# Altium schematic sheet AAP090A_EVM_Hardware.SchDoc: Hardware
size Letter; Date: Not shown in title block; ApprovedBy: Not shown in title block; CheckedBy: Not shown in title block; Author: Not shown in title block; CompanyName: Not shown in title block; DrawnBy: LDN; Engineer: Not shown in title block; Organization: Not shown in title block; Address1: Not shown in title block; Address2: Not shown in title block; Address3: Not shown in title block; Address4: Not shown in title block; DocumentNumber: 6; Revision: Use project parameter SCH_Rev; SheetNumber: 6; SheetTotal: 6; PageSetup: Record=PageOptions¦CenterHorizontal=True¦CenterVertical=True¦PrintScale=1.00¦XCorrection=1.00¦YCorrection=1.00¦PrintKind=0¦BorderSize=5000000¦LeftOffset=0¦BottomOffset=0¦Orientation=2¦PaperLength=1000¦PaperWidth=1000¦Scale=100¦PaperSource=15¦PrintQuality=600¦MediaType=1¦DitherType=10¦PaperKind=Letter¦PrintScaleMode=1
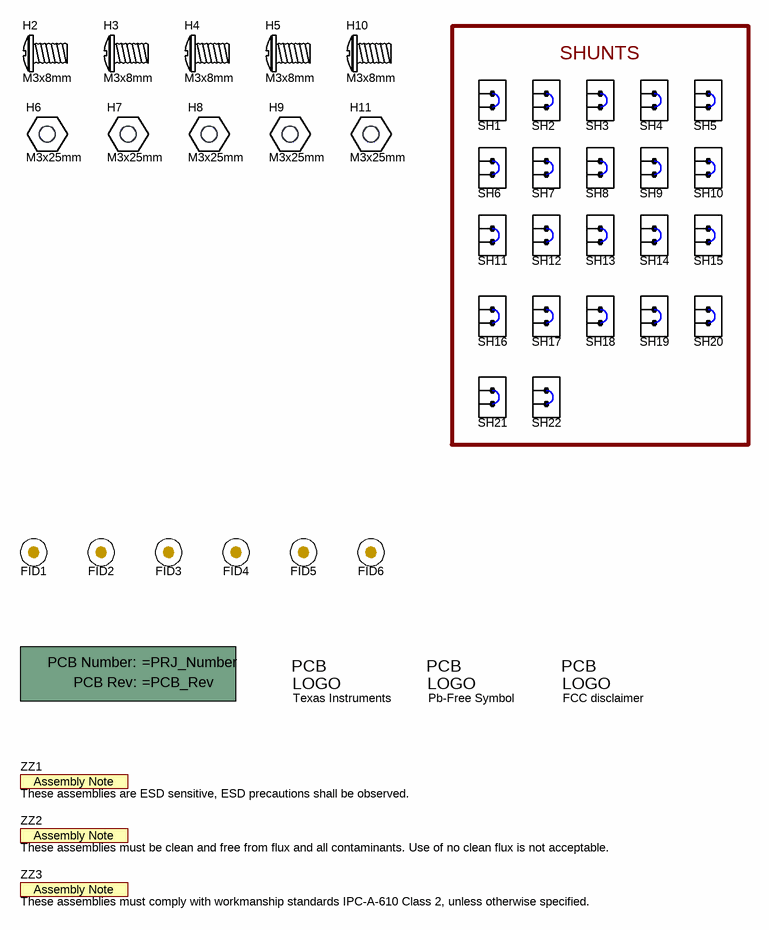
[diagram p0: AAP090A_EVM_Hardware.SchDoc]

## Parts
!PCB  Printed Circuit Board  (value not drawn)  (mechanical)
FID1  Fiducial  [Fiducial10-20]  (value not drawn)
FID2  Fiducial  [Fiducial10-20]  (value not drawn)
FID3  Fiducial  [Fiducial10-20]  (value not drawn)
FID4  Fiducial  [Fiducial10-20]  (value not drawn)
FID5  Fiducial  [Fiducial10-20]  (value not drawn)
FID6  Fiducial  [Fiducial10-20]  (value not drawn)
H2  M3x8mm  [APM_RM3X8MM 2701]
H3  M3x8mm  [APM_RM3X8MM 2701]
H4  M3x8mm  [APM_RM3X8MM 2701]
H5  M3x8mm  [APM_RM3X8MM 2701]
H6  M3x25mm  [Keystone24438]
H7  M3x25mm  [Keystone24438]
H8  M3x25mm  [Keystone24438]
H9  M3x25mm  [Keystone24438]
H10  M3x8mm  [APM_RM3X8MM 2701]
H11  M3x25mm  [Keystone24438]
Logo1  Texas Instruments  [TI_Stacked_Overlay_Small]  (no BOM)
Logo2  Pb-Free Symbol  [Pb-Free_Overlay_Medium]  (no BOM)
Logo3  FCC disclaimer  [FCC_disclaimer]  (no BOM)
SH1  SNT-100-BK-G  [SNT-100-BK-G]  (value not drawn)
SH2  SNT-100-BK-G  [SNT-100-BK-G]  (value not drawn)
SH3  SNT-100-BK-G  [SNT-100-BK-G]  (value not drawn)
SH4  SNT-100-BK-G  [SNT-100-BK-G]  (value not drawn)
SH5  SNT-100-BK-G  [SNT-100-BK-G]  (value not drawn)
SH6  SNT-100-BK-G  [SNT-100-BK-G]  (value not drawn)
SH7  SNT-100-BK-G  [SNT-100-BK-G]  (value not drawn)
SH8  SNT-100-BK-G  [SNT-100-BK-G]  (value not drawn)
SH9  SNT-100-BK-G  [SNT-100-BK-G]  (value not drawn)
SH10  SNT-100-BK-G  [SNT-100-BK-G]  (value not drawn)
SH11  SNT-100-BK-G  [SNT-100-BK-G]  (value not drawn)
SH12  SNT-100-BK-G  [SNT-100-BK-G]  (value not drawn)
SH13  SNT-100-BK-G  [SNT-100-BK-G]  (value not drawn)
SH14  SNT-100-BK-G  [SNT-100-BK-G]  (value not drawn)
SH15  SNT-100-BK-G  [SNT-100-BK-G]  (value not drawn)
SH16  SNT-100-BK-G  [SNT-100-BK-G]  (value not drawn)
SH17  SNT-100-BK-G  [SNT-100-BK-G]  (value not drawn)
SH18  SNT-100-BK-G  [SNT-100-BK-G]  (value not drawn)
SH19  SNT-100-BK-G  [SNT-100-BK-G]  (value not drawn)
SH20  SNT-100-BK-G  [SNT-100-BK-G]  (value not drawn)
SH21  SNT-100-BK-G  [SNT-100-BK-G]  (value not drawn)
SH22  SNT-100-BK-G  [SNT-100-BK-G]  (value not drawn)
ZZ1  These assemblies are ESD sensitive, ESD precautions shall be observed.  [AssemblyNote]  (no BOM)
ZZ2  These assemblies must be clean and free from flux and all contaminants. Use of no clean flux is not acceptable.  [AssemblyNote]  (no BOM)
ZZ3  These assemblies must comply with workmanship standards IPC-A-610 Class 2, unless otherwise specified.  [AssemblyNote]  (no BOM)

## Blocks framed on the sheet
SHUNTS: SH1-SH22

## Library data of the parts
!PCB = PCB: Manufacturer: Any; SymbolCreator: a0412235
FID1-FID6 = Fiducial: Fiducial mark.  There is nothing to buy or mount.; SymbolCreator: codlsc
H2-H5 H10 = RM3X8MM 2701: MACHINE SCREW PAN PHILLIPS M3; Manufacturer: APM HEXSEAL; SymbolCreator: a0412235; CompType: Standoff
H6-H9 H11 = 24438: Standoff, Hex,25mm Length, M3, Aluminum; Manufacturer: Keystone; SymbolCreator: a0412235; Green_Lifecycle: Active; Green_REACh: Passed
Logo1 = TI_Logo: Texas Instrument Corporate Signature; SymbolCreator: codlsc
Logo2 = Pb-Free: SymbolCreator: a0412235
Logo3 = FCC_disclaimer: SymbolCreator: codlsc
SH1-SH22 = SNT-100-BK-G: Shunt, 100mil, Gold plated, Black; Manufacturer: Samtec; Alternate Manufacturer: 3M; Alternate PartNumber: 969102-0000-DA; Value: 1x2; Note: You can "mate" this to a header by matching the designator.  i.e. use SH-J3 for header J3; Green_Lifecycle: Active; Green_REACh: Passed
ZZ1-ZZ3 = AssemblyNote: SymbolCreator: codlsc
